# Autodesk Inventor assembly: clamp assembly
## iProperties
Shininess: 64.0
Length Units: 11272
Angle Units: 11279
Time Units: 11290
Mass Units: 11286
Length Display Precision: 3
Angle Display Precision: 2
Compacted: True
Part Number: clamp assembly
Document SubType Name: Assembly
Created: 2002-11
Designer: E. MOSS
Density: 0.0
Volumn: 0.0
Area: 0.0
PropertySet Name: Model Information
Control State: 0
Master: False
Checked Out: False
Author: E. MOSS
